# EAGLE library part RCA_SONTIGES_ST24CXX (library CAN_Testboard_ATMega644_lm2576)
IC EEPROM Bei den Atmeltypen ist der A2-Pin nicht angeschlossen! Bisher berprfte Gren: ST24C32 (4 kByte) ST24C64 (8 kByte) ST24C128 (16 kByte) ST24C256 (32 kByte)
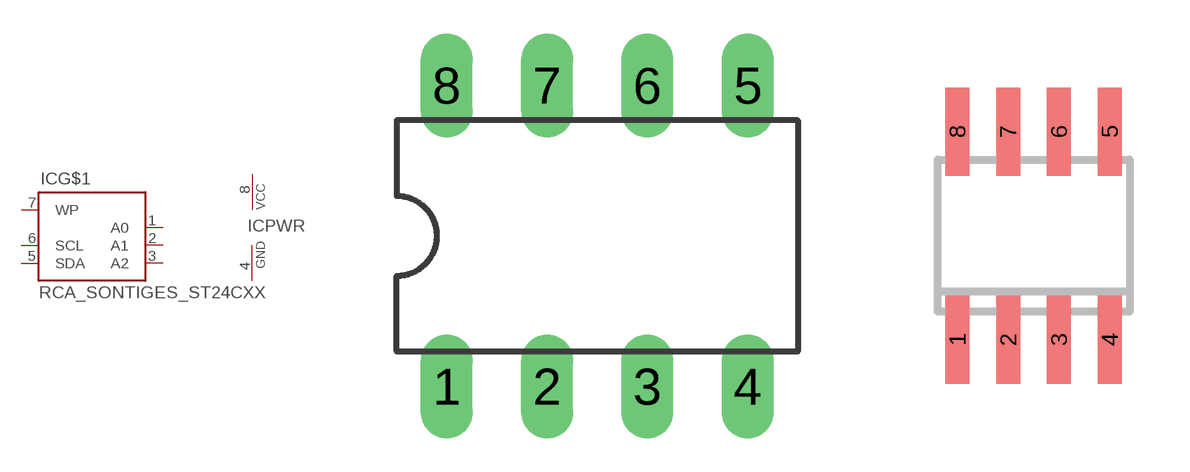
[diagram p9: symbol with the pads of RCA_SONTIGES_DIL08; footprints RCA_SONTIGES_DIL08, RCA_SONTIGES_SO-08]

Designator prefix IC; gates G$1=RCA_SONTIGES_ST24CXX PWR=RCA_SONTIGES_PWRN

## RCA_SONTIGES_ST24CXX_DIP  [RCA_SONTIGES_DIL08]
1  G$1:A0  in
2  G$1:A1  in
3  G$1:A2  in
4  PWR:GND  pwr
5  G$1:SDA
6  G$1:SCL  in
7  G$1:WP  in
8  PWR:VCC  pwr

## RCA_SONTIGES_ST24CXX_SMD  [RCA_SONTIGES_SO-08]
Pads as for RCA_SONTIGES_DIL08

## Footprint RCA_SONTIGES_DIL08 (pad centres in mm)
Dual In Line Package
drill 0.813 long: 1 -3.81,-3.81; 2 -1.27,-3.81; 3 1.27,-3.81; 4 3.81,-3.81; 5 3.81,3.81; 6 1.27,3.81; 7 -1.27,3.81; 8 -3.81,3.81

## Footprint RCA_SONTIGES_SO-08 (pad centres in mm)
Small Outline Narrow Plastic Gull Wing 150-mil body, package type SN
smd 0.6 x 2.2: 1 -1.905,-2.6; 2 -0.635,-2.6; 3 0.635,-2.6; 4 1.905,-2.6; 5 1.905,2.6; 6 0.635,2.6; 7 -0.635,2.6; 8 -1.905,2.6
